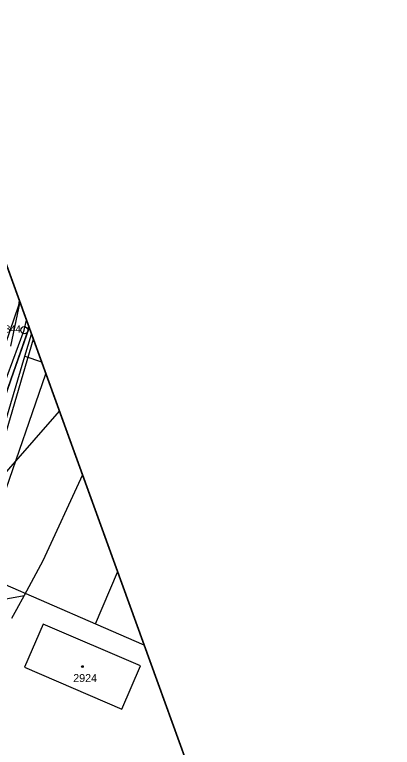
# Model space of a CAD drawing. Extents: x -620552 to -620056, y -1123312 to -1122890.
# Drawn here: x -620136.2 to -620056.1, y -1123045.1 to -1122889.6 of the extents above; entities that cross this region are included whole.
import ezdxf

# ---------------------------------------------------------------- set-up
doc = ezdxf.new("R2010")
doc.units = 0
for name, color, linetype in [('HranDP', 7, 'Continuous'), ('Hranice parcel', 7, 'Continuous'), ('Parcelní čísla', 7, 'Continuous'), ('Rámečky', 7, 'Continuous'), ('Rámečky-tisk', 7, 'Continuous'), ('SSZT', 7, 'Continuous'), ('SSZT-DK', 7, 'Continuous'), ('SSZT-OSS', 7, 'Continuous'), ('SSZT-TK', 7, 'Continuous'), ('VAS el kabel', 7, 'Continuous'), ('VAS vodovod', 7, 'Continuous'), ('Značky bodu BP', 7, 'Continuous'), ('Značky budov', 7, 'Continuous'), ('ČD-T', 7, 'Continuous')]:
    doc.layers.add(name, color=color, linetype=linetype)

msp = doc.modelspace()

# ---------------------------------------------------------------- linework, layer by layer
at = {"layer": 'HranDP'}
msp.add_lwpolyline([(-620139.01, -1122969.61), (-620134.15, -1122956.58), (-620133.7, -1122954.48)], dxfattribs=at)
at = {"layer": 'Hranice parcel'}
msp.add_line((-620138.43, -1123013.68), (-620134.2, -1123012.93), dxfattribs=at)
for points in [[(-620139.01, -1122969.61), (-620134.15, -1122956.58), (-620133.7, -1122954.48)], [(-620121.82, -1122987.28), (-620130.2, -1123005.56), (-620134.2, -1123012.93)], [(-620134.2, -1123012.93), (-620135.79, -1123015.87), (-620136.85, -1123017.81)], [(-620134.13, -1123028.15), (-620113.42, -1123037.02), (-620109.47, -1123027.84), (-620130.15, -1123018.97), (-620134.13, -1123028.15)]]:
    msp.add_lwpolyline(points, dxfattribs=at)
at = {"layer": 'Rámečky'}
msp.add_line((-620056.07, -1123168.86), (-620157.19, -1122889.6), dxfattribs=at)
for points in [[(-620126.7, -1122973.8), (-620157.19, -1122889.6), (-620255.57, -1122925.22)], [(-620255.57, -1122925.22), (-620158.49, -1123010.14), (-620126.7, -1122973.8)]]:
    msp.add_lwpolyline(points, dxfattribs=at)
at = {"layer": 'Rámečky-tisk'}
for points in [[(-620450.98, -1123311.85), (-620056.07, -1123168.86), (-620157.19, -1122889.6), (-620552.1, -1123032.6)], [(-620126.7, -1122973.8), (-620157.19, -1122889.6), (-620255.57, -1122925.22)], [(-620255.57, -1122925.22), (-620158.49, -1123010.14), (-620126.7, -1122973.8)]]:
    msp.add_lwpolyline(points, dxfattribs=at)
at = {"layer": 'SSZT'}
msp.add_lwpolyline([(-620135.22, -1122950.28), (-620135.4, -1122951.34), (-620146.6, -1122984.04), (-620154, -1123000.74), (-620159.53, -1122998.12), (-620166.88, -1123010.24)], dxfattribs=at)
at = {"layer": 'SSZT-DK'}
msp.add_lwpolyline([(-620133.24, -1122955.74), (-620133.43, -1122956.64), (-620137.1, -1122967.18), (-620142.13, -1122981.67), (-620150.09, -1123001.93), (-620153.27, -1123011.66), (-620162.86, -1123027.53), (-620167.45, -1123035.13), (-620177.31, -1123046.87), (-620183.14, -1123053.82), (-620203.25, -1123073.11), (-620220.92, -1123087.08), (-620234.47, -1123097), (-620250.94, -1123106.67), (-620258.73, -1123108.48), (-620268.16, -1123109.67), (-620277.94, -1123110.89), (-620291.83, -1123110.91), (-620302.99, -1123111.77)], dxfattribs=at)
at = {"layer": 'SSZT-OSS'}
msp.add_lwpolyline([(-620135.12, -1122950.56), (-620137.06, -1122959.97)], dxfattribs=at)
at = {"layer": 'SSZT-TK'}
msp.add_lwpolyline([(-620135.22, -1122950.28), (-620135.4, -1122951.34), (-620146.6, -1122984.04), (-620155.29, -1123003.62), (-620165.83, -1123021.36), (-620186.83, -1123047.79), (-620210, -1123069.75), (-620240.2, -1123085.98), (-620267.98, -1123097.08), (-620292.31, -1123104.15), (-620332.1, -1123112.12), (-620382.38, -1123122.06), (-620466.84, -1123137.57), (-620511.01, -1123146.08)], dxfattribs=at)
at = {"layer": 'VAS el kabel'}
msp.add_lwpolyline([(-620147.57, -1123004.63), (-620147.62, -1123004.57), (-620147.67, -1123004.52), (-620146.94, -1123003.53), (-620146.21, -1123002.55), (-620144.9, -1123002.04), (-620143.59, -1123001.52), (-620142.59, -1123000.52), (-620141.6, -1122999.52), (-620141.11, -1122998.41), (-620140.63, -1122997.3), (-620139.67, -1122994.81), (-620138.72, -1122992.31), (-620129.59, -1122965.83)], dxfattribs=at)
at = {"layer": 'VAS vodovod'}
for p, q in [((-620145.87, -1123007.26), (-620119.03, -1123018.9)), ((-620119.03, -1123018.9), (-620114.34, -1123007.93)), ((-620119.03, -1123018.9), (-620108.76, -1123023.35))]:
    msp.add_line(p, q, dxfattribs=at)
for points in [[(-620148.37, -1123002.79), (-620148.32, -1123002.65), (-620148.28, -1123002.5), (-620145.95, -1122998.54), (-620143.63, -1122994.58), (-620138.82, -1122978.35), (-620134.02, -1122962.12), (-620132.63, -1122957.42)], [(-620132.23, -1122958.52), (-620142.96, -1122994.78), (-620143.11, -1122995.22), (-620143.26, -1122995.66), (-620143.32, -1122996.57), (-620143.37, -1122997.48), (-620143.78, -1122998.76), (-620144.18, -1123000.04)], [(-620134.02, -1122962.12), (-620130.51, -1122963.27)]]:
    msp.add_lwpolyline(points, dxfattribs=at)
at = {"layer": 'Značky bodu BP'}
for radius in [0.75, 0.03]:
    msp.add_circle((-620134.15, -1122956.58), radius, dxfattribs=at)
at = {"layer": 'Značky budov'}
msp.add_circle((-620121.81, -1123027.99), 0.175, dxfattribs=at)
at = {"layer": 'ČD-T'}
msp.add_lwpolyline([(-620133.15, -1122955.98), (-620133.25, -1122956.41), (-620136.91, -1122966.94), (-620141.94, -1122981.44), (-620149.9, -1123001.7), (-620153.17, -1123011.69), (-620162.64, -1123027.32), (-620167.44, -1123035.18), (-620176.91, -1123046.42), (-620183.1, -1123053.85), (-620203.17, -1123073.24), (-620220.83, -1123087.24), (-620234.31, -1123097.18), (-620250.89, -1123107.04), (-620258.79, -1123108.89), (-620268.53, -1123110.05), (-620277.75, -1123111.28), (-620291.59, -1123111.44), (-620302.16, -1123112.16)], dxfattribs=at)

# ---------------------------------------------------------------- texts
at = {"layer": 'Parcelní čísla'}
msp.add_text('2924', height=1.7, dxfattribs=at).set_placement((-620123.77, -1123031.28))
at = {"layer": 'Značky bodu BP'}
msp.add_text('844', height=1.5, dxfattribs=at).set_placement((-620138.25, -1122957.08))

doc.saveas('drawing.dxf')
